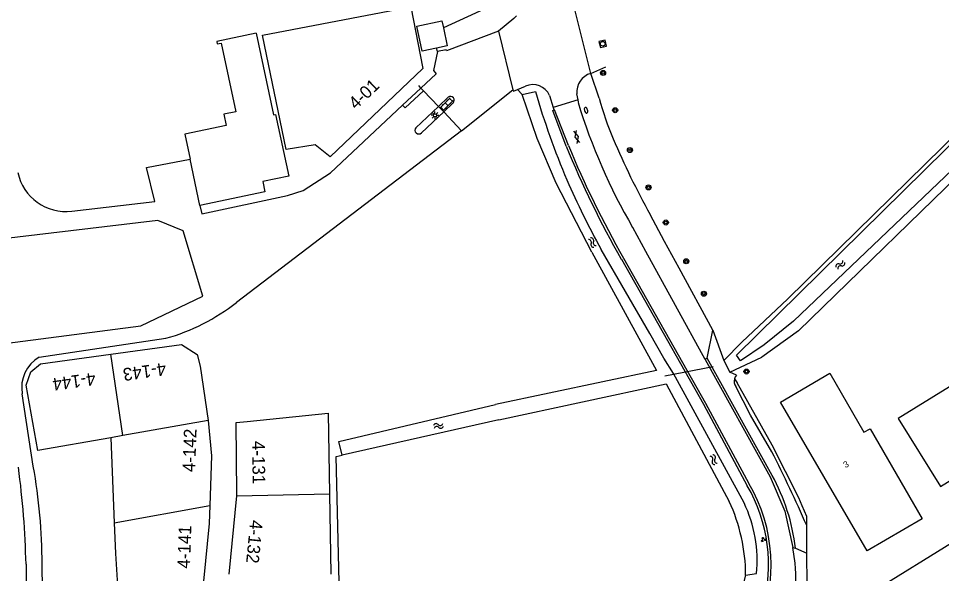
# Model space of a CAD drawing. Extents: x 134297 to 137000, y 403500 to 406000.
# Drawn here: x 136271.5 to 136417.4, y 405248.5 to 405336.3 of the extents above; entities that cross this region are included whole.
import ezdxf

# ---------------------------------------------------------------- set-up
doc = ezdxf.new("R2010")
doc.units = 0
for name, color, linetype in [('gg-afsc-draadraster', 7, 'Continuous'), ('gg-afsc-erfafscheiding', 7, 'Continuous'), ('gg-afsc-hekwerk', 7, 'Continuous'), ('gg-afsc-lijn draadraster', 7, 'Continuous'), ('gg-anno-huisnummerreeks BGT', 7, 'Continuous'), ('gg-bbg-bijgebouw', 7, 'Continuous'), ('gg-bbg-gedigitaliseerde bebouwing', 7, 'Continuous'), ('gg-bbg-gedigitaliseerde bijgebouw', 7, 'Continuous'), ('gg-bbg-hoofdgebouw', 7, 'Continuous'), ('gg-knt-verharding', 7, 'Continuous'), ('gg-knt-verharding nz', 7, 'Continuous'), ('gg-kntw-bovenkant insteek waterloop', 7, 'Continuous'), ('gg-kntw-waterlijn', 7, 'Continuous'), ('gg-kwrk-duiker nz buis', 7, 'Continuous'), ('gt-afsc-standplaatsafbakening', 7, 'Continuous'), ('gt-anno-standplaatsnummer', 7, 'Continuous'), ('gt-grn-groengrens', 7, 'Continuous'), ('gt-grn-vlakafsluiter', 7, 'Continuous'), ('gt-symb-boom', 7, 'Continuous'), ('gt-symb-brandkraan', 7, 'Continuous'), ('gt-symb-gesloten verharding', 7, 'Continuous'), ('gt-symb-groenvak', 7, 'Continuous'), ('gt-symb-klinker verharding', 7, 'Continuous'), ('gt-symb-lichtmast', 7, 'Continuous'), ('gt-symb-rioolschacht', 7, 'Continuous'), ('gt-symb-watersymbool', 7, 'Continuous')]:
    doc.layers.add(name, color=color, linetype=linetype)

# ---------------------------------------------------------------- blocks, each defined once
blk = doc.blocks.new('gt0-WA')
at = {"layer": 'gt-symb-watersymbool'}
for centre, start, end in [((-0.32, 0.02), 28.0725, 151.9275), ((0.43, 0.42), 208.0725, 331.9275), ((-0.32, -0.43), 28.0725, 151.9275), ((0.43, -0.03), 208.0725, 331.9275)]:
    blk.add_arc(centre, 0.425, start, end, dxfattribs=at)
blk = doc.blocks.new('gt0-GRVAK')
at = {"layer": 'gt-symb-groenvak'}
for p, q in [((-0.11, 0.19), (-0.23, 0.24)), ((-0.18, 0.15), (0.09, 0.15)), ((-0.09, 0.21), (-0.16, 0.32)), ((-0.05, 0.21), (-0.05, 0.39)), ((0, 0.21), (0.06, 0.32)), ((0.01, 0.19), (0.13, 0.24)), ((0.26, -0.05), (0.2, 0.06)), ((0.3, -0.05), (0.3, 0.13)), ((0.35, -0.05), (0.41, 0.06)), ((-0.24, -0.23), (-0.36, -0.18)), ((-0.32, -0.26), (-0.05, -0.26)), ((-0.23, -0.21), (-0.29, -0.09)), ((-0.18, -0.2), (-0.18, -0.02)), ((-0.14, -0.21), (-0.07, -0.09)), ((-0.12, -0.23), (0, -0.18)), ((0.24, -0.07), (0.12, -0.02)), ((0.17, -0.11), (0.44, -0.11)), ((0.37, -0.07), (0.49, -0.02))]:
    blk.add_line(p, q, dxfattribs=at)
blk = doc.blocks.new('gt0-BOOM')
at = {"layer": 'gt-symb-boom'}
for radius in [0.4, 0.2]:
    blk.add_circle((0, 0), radius, dxfattribs=at)
blk = doc.blocks.new('gt0-RS')
at = {"layer": 'gt-symb-rioolschacht'}
blk.add_lwpolyline([(-0.5, -0.5), (0.5, -0.5), (0.5, 0.5), (-0.5, 0.5)], close=True, dxfattribs=at)
blk.add_circle((0, 0), 0.375, dxfattribs=at)
blk = doc.blocks.new('gt0-GESVH1')
at = {"layer": 'gt-symb-gesloten verharding'}
for p, q in [((-0.99, -0.26), (0.01, 0.24)), ((0.01, -0.26), (-0.99, 0.24)), ((0.01, 0.24), (1.01, -0.26)), ((1.01, 0.24), (0.01, -0.26))]:
    blk.add_line(p, q, dxfattribs=at)
blk = doc.blocks.new('gt0-BR')
at = {"layer": 'gt-symb-brandkraan'}
for centre, radius, start, end in [((-0.24, 0), 0.206, 107.5669, 252.4331), ((0.6, -2.66), 3, 106.892, 107.5669), ((0, -0.69), 0.938, 73.108, 106.892), ((-0.6, -2.66), 3, 72.4331, 73.108), ((0.24, 0), 0.206, 287.567, 72.4331), ((0.6, 2.66), 3, 252.4331, 253.108), ((0, 0.69), 0.938, 253.108, 286.8921), ((-0.6, 2.66), 3, 286.8921, 287.567)]:
    blk.add_arc(centre, radius, start, end, dxfattribs=at)
blk = doc.blocks.new('gt0-LMAST')
at = {"layer": 'gt-symb-lichtmast'}
for p, q in [((-0.18, 0.17), (-0.45, 0.44)), ((-0.01, 0.25), (-0.01, 0.62)), ((0.17, 0.17), (0.44, 0.44)), ((-0.26, 0), (-0.63, 0)), ((-0.18, -0.18), (-0.45, -0.45)), ((-0.01, -0.25), (-0.01, -0.63)), ((0.44, -0.45), (0.17, -0.18)), ((0.24, 0), (0.62, 0))]:
    blk.add_line(p, q, dxfattribs=at)
blk.add_circle((-0.01, 0), 0.25, dxfattribs=at)
blk = doc.blocks.new('gt0-KL1')
at = {"layer": 'gt-symb-klinker verharding'}
for p, q in [((-1.15, 0.3), (1.15, 0.3)), ((-1, -0.3), (-1, 0.3)), ((-0.5, 0.3), (-0.5, 0.45)), ((0, -0.3), (0, 0.3)), ((0.5, 0.3), (0.5, 0.45)), ((1, -0.3), (1, 0.3)), ((-1.15, -0.3), (1.15, -0.3)), ((-0.5, -0.45), (-0.5, -0.3)), ((0.5, -0.45), (0.5, -0.3))]:
    blk.add_line(p, q, dxfattribs=at)

msp = doc.modelspace()

# ---------------------------------------------------------------- linework, layer by layer
at = {"layer": 'gg-afsc-draadraster'}
msp.add_lwpolyline([(136386.43, 405248.24), (136385.52, 405244.75), (136383.99, 405240.63), (136380.91, 405236.12), (136373.59, 405230.5), (136323.43, 405196.31), (136321.74, 405266.99), (136322.69, 405267.21)], dxfattribs=at)
at = {"layer": 'gg-afsc-erfafscheiding'}
msp.add_line((136384.67, 405279.29), (136385.08, 405278.68), dxfattribs=at)
msp.add_lwpolyline([(136395.35, 405259.21), (136394.81, 405260.49), (136390.6, 405268.79), (136385.08, 405278.68)], dxfattribs=at)
at = {"layer": 'gg-afsc-hekwerk'}
for p, q in [((136335.13, 405325.29), (136334.77, 405325.68)), ((136335.54, 405324.86), (136335.13, 405325.29)), ((136337.9, 405322.37), (136335.54, 405324.86)), ((136337.9, 405322.37), (136335.54, 405324.86)), ((136338.72, 405321.5), (136337.9, 405322.37)), ((136341.55, 405318.51), (136338.72, 405321.5)), ((136341.55, 405318.51), (136338.72, 405321.5))]:
    msp.add_line(p, q, dxfattribs=at)
at = {"layer": 'gg-afsc-lijn draadraster'}
msp.add_lwpolyline([(136386.43, 405248.24), (136385.52, 405244.75), (136383.99, 405240.63), (136380.91, 405236.12), (136373.59, 405230.5), (136323.43, 405196.31), (136321.74, 405266.99), (136322.69, 405267.21)], dxfattribs=at)
at = {"layer": 'gg-bbg-bijgebouw'}
for points in [[(136334.48, 405335.06), (136338.43, 405335.91), (136338.67, 405334.78)], [(136309.12, 405333.94), (136311.84, 405321.06), (136312.15, 405321.12), (136314.24, 405311.34), (136310.14, 405310.52), (136310.48, 405308.89), (136300.21, 405306.7)], [(136337.6, 405331.6), (136335.32, 405331.11), (136334.48, 405335.06)], [(136338.67, 405334.78), (136339.27, 405331.96), (136337.6, 405331.6)]]:
    msp.add_lwpolyline(points, dxfattribs=at)
at = {"layer": 'gg-bbg-gedigitaliseerde bebouwing'}
msp.add_lwpolyline([(136399.72, 405280.17), (136405.11, 405270.84), (136406.08, 405271.4), (136414.31, 405257.13), (136405.61, 405252.11)], dxfattribs=at)
at = {"layer": 'gg-bbg-gedigitaliseerde bijgebouw'}
msp.add_line((136300.21, 405306.7), (136298.65, 405314.05), dxfattribs=at)
for points in [[(136309.12, 405333.94), (136302.86, 405332.62), (136302.94, 405332.25), (136303.56, 405332.39), (136305.86, 405321.54), (136303.99, 405321.14), (136304.36, 405319.36), (136297.82, 405317.97), (136298.65, 405314.05)], [(136410.55, 405273.02), (136417.21, 405262.25), (136427.21, 405268.43), (136425.79, 405270.73), (136442.58, 405281.1), (136437.35, 405289.57), (136410.55, 405273.02)], [(136415.83, 405232.11), (136442.06, 405248.4), (136435.09, 405259.7), (136420.57, 405250.73), (136418.95, 405253.33), (136407.19, 405246.01)]]:
    msp.add_lwpolyline(points, dxfattribs=at)
at = {"layer": 'gg-bbg-hoofdgebouw'}
msp.add_lwpolyline([(136405.61, 405252.11), (136391.96, 405275.6), (136399.72, 405280.17)], dxfattribs=at)
at = {"layer": 'gg-knt-verharding'}
for p, q in [((136348.25, 405339.18), (136338.67, 405334.78)), ((136361.98, 405327.59), (136359.08, 405339.26)), ((136347.38, 405334.29), (136349.67, 405325)), ((136337.72, 405331.04), (136337.6, 405331.6)), ((136361.98, 405327.59), (136364.33, 405328.63)), ((136335.13, 405325.29), (136337.51, 405327.53)), ((136363.29, 405323.68), (136361.98, 405327.59)), ((136332.24, 405322.58), (136335.13, 405325.29)), ((136341.55, 405318.51), (136349.67, 405325)), ((136350.39, 405325.05), (136351.64, 405325.58)), ((136337.9, 405322.37), (136339.44, 405323.82)), ((136355.45, 405324.11), (136356.02, 405322.2)), ((136359.98, 405323.4), (136359.78, 405324.37)), ((136334.33, 405319.01), (136337.9, 405322.37)), ((136340.21, 405322.92), (136338.72, 405321.5)), ((136359.98, 405323.4), (136356.02, 405322.2)), ((136359.95, 405323.02), (136360.01, 405323.03)), ((136360.01, 405323.03), (136359.98, 405323.4)), ((136338.72, 405321.5), (136335.21, 405318.19)), ((136356.22, 405321.82), (136356.21, 405321.85)), ((136358.43, 405316.22), (136356.22, 405321.82)), ((136341.55, 405318.51), (136305.98, 405291.37)), ((136381.24, 405286.97), (136375.9, 405296.78)), ((136274.82, 405282.73), (136294.84, 405285.71)), ((136380.36, 405282.54), (136381.24, 405286.97)), ((136390.63, 405264.02), (136380.36, 405282.54)), ((136273.88, 405265.46), (136272.14, 405276.93)), ((136394.23, 405250.13), (136393.87, 405252.64)), ((136394.32, 405252.49), (136396.11, 405251.75))]:
    msp.add_line(p, q, dxfattribs=at)
for points in [[(136350.24, 405336.73), (136349.79, 405336.28), (136347.38, 405334.29)], [(136347.38, 405334.29), (136339.17, 405331.18), (136339.12, 405331.34), (136337.72, 405331.04)], [(136337.72, 405331.04), (136337.1, 405328.06), (136337.51, 405327.53)], [(136349.67, 405325), (136349.74, 405324.77), (136350.39, 405325.05)], [(136335.54, 405324.86), (136332.66, 405322.15), (136332.24, 405322.58)], [(136300.21, 405306.7), (136300.5, 405305.37), (136314.04, 405308.29), (136316.51, 405309.07), (136320.83, 405311.87), (136332.24, 405322.58)], [(136356.02, 405322.2), (136356.12, 405321.83), (136356.21, 405321.85)], [(136358.07, 405316.11), (136355.97, 405321.72), (136356.22, 405321.82)], [(136279.95, 405305.81), (136293.08, 405307.33), (136291.78, 405312.72)], [(136375.9, 405296.78), (136373.63, 405301.03), (136371.33, 405305.27)], [(136224.78, 405279.09), (136290.86, 405287.7), (136300.66, 405292.36), (136297.55, 405302.7), (136293.57, 405304.31), (136221.68, 405295.78), (136224.78, 405279.09)], [(136380.02, 405282.35), (136370.66, 405299.42), (136368.58, 405303.25)], [(136366.79, 405298.2), (136379.75, 405275.29), (136386.69, 405262.39)], [(136367.14, 405298.39), (136380.08, 405275.47), (136386.95, 405262.74)], [(136380.02, 405282.35), (136390.31, 405263.82), (136392.63, 405258.38), (136393.87, 405252.64)], [(136272.74, 405249.97), (136273.04, 405213.57), (136275.75, 405213.78), (136275.28, 405249.97)]]:
    msp.add_lwpolyline(points, dxfattribs=at)
for centre, radius, start, end in [((136362.79, 405324.68), 3.03, 105.656, 185.7735), ((136352.79, 405322.89), 2.93, 24.7467, 113.2649), ((136339.81, 405323.35), 0.593, 313.2943, 127.5306), ((136415.53, 405338.04), 54.18, 195.3636, 202.5472), ((136449.95, 405350.52), 94.11, 196.9931, 210.154), ((136334.79, 405318.62), 0.603, 139.3021, 313.9288), ((136498.91, 405373.78), 151.82, 202.2798, 209.7732), ((136485.38, 405368.19), 130.25, 203.0152, 208.8854), ((136501.09, 405374.65), 154.54, 202.2609, 209.6495), ((136279.06, 405313.54), 7.78, 191.9199, 276.6121), ((136286.19, 405316.53), 32.01, 285.6765, 308.1958), ((136277.62, 405277.92), 5.57, 120.1734, 190.1711), ((136133.98, 405246.83), 138.79, 1.2961, 7.6476), ((136187.94, 405249.89), 87.34, 0.0519, 10.269), ((136361.99, 405248.51), 32.57, 7.0331, 28.4569), ((136365.08, 405249.89), 24.97, 344.7146, 30.0525), ((136365.21, 405249.92), 25.24, 336.2169, 30.5411), ((136374.85, 405247.74), 19.53, 328.8731, 7.0083)]:
    msp.add_arc(centre, radius, start, end, dxfattribs=at)
at = {"layer": 'gg-knt-verharding nz'}
for p, q in [((136380.36, 405282.54), (136380.02, 405282.35)), ((136393.87, 405252.64), (136394.32, 405252.49))]:
    msp.add_line(p, q, dxfattribs=at)
at = {"layer": 'gg-kntw-bovenkant insteek waterloop'}
for p, q in [((136351.1, 405324.24), (136353.23, 405324.73)), ((136385.8, 405285.07), (136393.11, 405291.96)), ((136394.76, 405286.89), (136388.97, 405282.74)), ((136385.8, 405285.07), (136382.98, 405282.19)), ((136383.94, 405280.35), (136388.97, 405282.74)), ((136382.98, 405282.19), (136383.94, 405280.35)), ((136347.45, 405272.8), (136322.69, 405267.21)), ((136386.43, 405248.24), (136388.15, 405248.5))]:
    msp.add_line(p, q, dxfattribs=at)
for points in [[(136393.11, 405291.96), (136420.23, 405318.56), (136436.7, 405334.16), (136460.48, 405324.48), (136481.21, 405312.57), (136493.09, 405303.27), (136497.27, 405301.19), (136504.36, 405299.2), (136511.68, 405299.2), (136532.79, 405293.36)], [(136394.76, 405286.89), (136423.79, 405315.15), (136438.39, 405328.6), (136457.65, 405320.1), (136466.29, 405315.69), (136478.9, 405307.87), (136491.61, 405298.6), (136496, 405296.59), (136498.6, 405296.11)], [(136362.12, 405299.31), (136356.5, 405310.26), (136353.49, 405317.3), (136351.1, 405324.24)], [(136362.12, 405299.31), (136372.32, 405280.63), (136346.9, 405275.25)], [(136386.18, 405259.68), (136375.03, 405280.12), (136373.5, 405282.54), (136371.3, 405286.47), (136363.61, 405299.75)], [(136347.45, 405272.8), (136373.85, 405278.48), (136383.83, 405259.92)], [(136322.69, 405267.21), (136322.17, 405269.39), (136346.9, 405275.25)]]:
    msp.add_lwpolyline(points, dxfattribs=at)
for centre, radius, start, end in [((136470.08, 405358.3), 121.58, 196.0292, 203.0265), ((136488.84, 405368.31), 142.77, 203.7757, 208.6983), ((136358.2, 405248.09), 28.23, 0.3061, 24.7557), ((136366.99, 405250.53), 21.26, 354.5167, 25.4916)]:
    msp.add_arc(centre, radius, start, end, dxfattribs=at)
at = {"layer": 'gg-kntw-waterlijn'}
for points in [[(136385, 405283.06), (136424.54, 405321.97)], [(136422.52, 405315.66), (136394, 405288.41), (136389.38, 405284.68), (136385.61, 405282.15), (136385, 405283.06)]]:
    msp.add_lwpolyline(points, dxfattribs=at)
at = {"layer": 'gg-kwrk-duiker nz buis'}
msp.add_line((136381.3, 405281.19), (136373.64, 405279.72), dxfattribs=at)
at = {"layer": 'gt-afsc-standplaatsafbakening'}
for p, q in [((136288.05, 405270.34), (136286.16, 405283.2)), ((136301.51, 405272.72), (136288.05, 405270.34)), ((136286.11, 405269.99), (136274.59, 405267.96)), ((136288.05, 405270.34), (136286.11, 405269.99)), ((136286.11, 405269.99), (136286.65, 405256.54)), ((136304.81, 405248.41), (136306.03, 405260.8)), ((136306.03, 405260.8), (136320.68, 405261.11)), ((136320.68, 405261.11), (136320.9, 405248.41)), ((136286.65, 405256.54), (136301.77, 405259.26))]:
    msp.add_line(p, q, dxfattribs=at)
for points in [[(136310.09, 405333.63), (136333.54, 405338.14), (136335.41, 405328.4), (136320.78, 405314.43), (136318.4, 405316.32), (136313.85, 405315.54), (136310.09, 405333.63)], [(136286.16, 405283.2), (136297.29, 405284.75), (136299.75, 405283.13), (136300.27, 405281.28), (136301.51, 405272.72)], [(136274.59, 405267.96), (136272.77, 405278.28), (136273.48, 405280.39), (136275.02, 405281.65), (136286.16, 405283.2)], [(136307.67, 405272.56), (136320.46, 405273.87), (136320.68, 405261.11)], [(136301.51, 405272.72), (136302.05, 405267.12), (136301.77, 405259.26)], [(136306.03, 405260.8), (136306.06, 405261.1), (136305.92, 405272.41), (136307.67, 405272.56)], [(136301.77, 405259.26), (136301.68, 405256.41), (136300.77, 405247.32), (136300.73, 405245.28)], [(136286.65, 405256.54), (136286.85, 405251.66), (136287.31, 405244.9)]]:
    msp.add_lwpolyline(points, dxfattribs=at)
at = {"layer": 'gt-grn-groengrens'}
for p, q in [((136381.24, 405286.97), (136382.98, 405282.19)), ((136384.97, 405279.87), (136383.94, 405280.35))]:
    msp.add_line(p, q, dxfattribs=at)
msp.add_lwpolyline([(136390.57, 405267.77), (136387.19, 405273.57), (136384.87, 405278.06)], dxfattribs=at)
for centre, radius, start, end in [((136386.11, 405278.89), 1.5, 139.4894, 164.8068), ((136386.11, 405278.9), 1.49, 164.933, 214.0675), ((136170.17, 405156.49), 246.9, 23.797, 26.7875)]:
    msp.add_arc(centre, radius, start, end, dxfattribs=at)
at = {"layer": 'gt-grn-vlakafsluiter'}
for p, q in [((136351.1, 405324.24), (136350.39, 405325.05)), ((136291.78, 405312.72), (136298.65, 405314.05)), ((136396.11, 405251.75), (136396.08, 405256.12))]:
    msp.add_line(p, q, dxfattribs=at)
for points in [[(136396.08, 405256.12), (136396.07, 405257.53), (136395.35, 405259.21)], [(136395.6, 405239.25), (136396.18, 405241.83), (136396.11, 405251.75)]]:
    msp.add_lwpolyline(points, dxfattribs=at)

# ---------------------------------------------------------------- block references
at = {"layer": 'gt-symb-boom'}
for p in [(136363.91, 405327.68), (136365.81, 405321.78), (136368.15, 405315.48), (136371.08, 405309.58), (136373.82, 405304.02), (136377.04, 405297.89), (136379.83, 405292.75), (136386.56, 405280.45)]:
    msp.add_blockref('gt0-BOOM', p, dxfattribs=at)
at = {"layer": 'gt-symb-brandkraan', "rotation": -72.05443694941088}
msp.add_blockref('gt0-BR', (136361.22, 405321.76), dxfattribs=at)
at = {"layer": 'gt-symb-gesloten verharding', "rotation": 105.00891367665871}
msp.add_blockref('gt0-GESVH1', (136359.72, 405317.55), dxfattribs=at)
at = {"layer": 'gt-symb-groenvak', "rotation": 2.7508347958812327}
msp.add_blockref('gt0-GRVAK', (136389.24, 405253.87), dxfattribs=at)
at = {"layer": 'gt-symb-klinker verharding', "rotation": 45.04054902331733}
msp.add_blockref('gt0-KL1', (136339.17, 405322.73), dxfattribs=at)
at = {"layer": 'gt-symb-lichtmast'}
msp.add_blockref('gt0-LMAST', (136337.35, 405320.97), dxfattribs=at)
at = {"layer": 'gt-symb-rioolschacht', "rotation": 12.534934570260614}
msp.add_blockref('gt0-RS', (136363.85, 405332.28), dxfattribs=at)
at = {"layer": 'gt-symb-watersymbool'}
for p, rotation in [((136362.23, 405300.79), 126.01052539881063), ((136401.43, 405297.35), -134.8379190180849), ((136337.95, 405271.85), -167.35314650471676), ((136381.36, 405266.55), -61.71863891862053)]:
    msp.add_blockref('gt0-WA', p, dxfattribs=dict(at, rotation=rotation))

# ---------------------------------------------------------------- texts
at = {"layer": 'gg-anno-huisnummerreeks BGT'}
msp.add_text('3', height=1, rotation=30.1, dxfattribs=at).set_placement((136402.21, 405265.15))
at = {"layer": 'gt-anno-standplaatsnummer'}
for s, rotation, p in [('4-01', 43.676, (136324.85, 405321.78)), ('4-143', 187.9098, (136294.72, 405281.87)), ('4-144', 187.9098, (136283.59, 405280.32)), ('4-142', 88.0306, (136299.45, 405264.53)), ('4-131', 270.686, (136308.46, 405269.47)), ('4-132', 264.3986, (136308.17, 405257.03)), ('4-141', 88.0306, (136298.63, 405249.27))]:
    msp.add_text(s, height=2, rotation=rotation, dxfattribs=at).set_placement(p)

doc.saveas('drawing.dxf')
